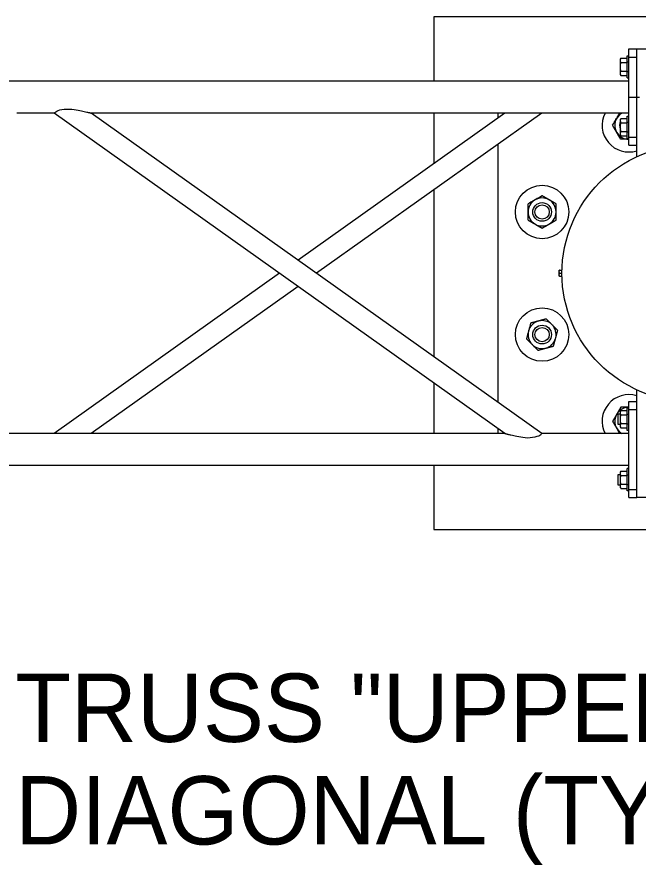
# Model space of a CAD drawing. Extents: x 99862 to 104211, y 98939 to 111076.
# Drawn here: x 101665.2 to 101810.6, y 101744.5 to 101943 of the extents above; entities that cross this region are included whole.
import ezdxf

# ---------------------------------------------------------------- set-up
doc = ezdxf.new("R2010")
doc.units = 0
for name, color, linetype in [('Level 2', 7, 'Continuous'), ('Level 20', 7, 'Continuous'), ('Level 3', 7, 'Continuous'), ('Level 4', 7, 'Continuous'), ('Level 5', 7, 'Continuous'), ('Level 6', 7, 'Continuous'), ('Level 9', 7, 'Continuous')]:
    doc.layers.add(name, color=color, linetype=linetype)

msp = doc.modelspace()

# ---------------------------------------------------------------- linework, layer by layer
at = {"layer": 'Level 2'}
for p, q in [((101882.76, 101942.97), (101762.76, 101942.97)), ((101762.76, 101942.97), (101762.76, 101927.97)), ((101762.76, 101920.47), (101762.76, 101908.62)), ((101777.76, 101920.47), (101777.76, 101919.29)), ((101777.76, 101913.15), (101777.76, 101852.78)), ((101762.76, 101902.49), (101762.76, 101863.45)), ((101762.76, 101857.31), (101762.76, 101845.47)), ((101777.76, 101846.65), (101777.76, 101845.47)), ((101762.76, 101837.97), (101762.76, 101822.97)), ((101762.76, 101822.97), (101882.76, 101822.97))]:
    msp.add_line(p, q, dxfattribs=at)
at = {"layer": 'Level 20'}
for p, q in [((101806.43, 101933.05), (101806.59, 101933.32)), ((101806.43, 101932.82), (101806.43, 101933.05)), ((101806.43, 101932.8), (101806.43, 101932.82)), ((101806.43, 101931.33), (101806.43, 101932.8)), ((101806.59, 101933.32), (101807.99, 101933.32)), ((101807.99, 101928.69), (101807.99, 101933.89)), ((101807.99, 101933.89), (101808.38, 101933.89)), ((101806.43, 101931.25), (101806.43, 101931.33)), ((101806.43, 101929.79), (101806.43, 101931.25)), ((101806.59, 101932.3), (101807.99, 101932.3)), ((101807.99, 101932.46), (101808.38, 101932.46)), ((101806.43, 101929.74), (101806.43, 101929.79)), ((101806.43, 101929.53), (101806.43, 101929.74)), ((101806.59, 101929.26), (101806.43, 101929.53)), ((101806.59, 101930.28), (101807.99, 101930.28)), ((101806.59, 101929.26), (101807.99, 101929.26)), ((101808.38, 101930.12), (101807.99, 101930.12)), ((101807.99, 101928.69), (101808.38, 101928.69)), ((101806.43, 101918.91), (101806.59, 101919.18)), ((101806.43, 101918.68), (101806.43, 101918.91)), ((101806.59, 101919.18), (101807.99, 101919.18)), ((101807.99, 101914.54), (101807.99, 101919.75)), ((101807.99, 101919.75), (101808.38, 101919.75)), ((101806.43, 101918.66), (101806.43, 101918.68)), ((101806.43, 101917.19), (101806.43, 101918.66)), ((101806.43, 101917.1), (101806.43, 101917.19)), ((101806.43, 101915.65), (101806.43, 101917.1)), ((101806.59, 101918.16), (101807.99, 101918.16)), ((101807.99, 101918.32), (101808.38, 101918.32)), ((101805.59, 101915.94), (101805.54, 101916.01)), ((101806.43, 101915.6), (101806.43, 101915.65)), ((101806.43, 101915.39), (101806.43, 101915.6)), ((101806.59, 101915.12), (101806.43, 101915.39)), ((101806.59, 101916.13), (101807.99, 101916.13)), ((101806.59, 101915.12), (101807.99, 101915.12)), ((101808.38, 101915.98), (101807.99, 101915.98)), ((101807.99, 101914.54), (101808.38, 101914.54)), ((101808.38, 101914.33), (101808.33, 101914.33)), ((101789.79, 101900.14), (101789.71, 101900.18)), ((101791.39, 101897.24), (101791.39, 101897.4)), ((101786.41, 101894.51), (101786.53, 101894.44)), ((101789.67, 101894.43), (101789.83, 101894.52)), ((101787.3, 101871.8), (101787.22, 101871.77)), ((101790.49, 101870.88), (101790.37, 101870.99)), ((101791.26, 101867.68), (101791.3, 101867.85)), ((101788.89, 101865.43), (101789.03, 101865.47)), ((101807.99, 101846.19), (101807.99, 101851.39)), ((101808.38, 101851.39), (101807.99, 101851.39)), ((101805.59, 101850), (101805.54, 101849.93)), ((101805.83, 101849.96), (101805.83, 101849.24)), ((101806.43, 101849.96), (101805.83, 101849.96)), ((101806.43, 101850.55), (101806.59, 101850.82)), ((101806.43, 101850.32), (101806.43, 101850.55)), ((101806.43, 101850.3), (101806.43, 101850.32)), ((101806.43, 101848.83), (101806.43, 101850.3)), ((101806.59, 101850.82), (101807.99, 101850.82)), ((101806.59, 101849.8), (101807.99, 101849.8)), ((101807.99, 101849.96), (101808.38, 101849.96)), ((101805.83, 101849.24), (101805.83, 101847.62)), ((101805.83, 101847.62), (101806.43, 101847.62)), ((101806.43, 101848.75), (101806.43, 101848.83)), ((101806.43, 101847.29), (101806.43, 101848.75)), ((101806.59, 101847.78), (101807.99, 101847.78)), ((101808.38, 101847.62), (101807.99, 101847.62)), ((101806.43, 101847.24), (101806.43, 101847.29)), ((101806.43, 101847.03), (101806.43, 101847.24)), ((101806.59, 101846.76), (101806.43, 101847.03)), ((101806.59, 101846.76), (101807.99, 101846.76)), ((101808.38, 101846.19), (101807.99, 101846.19)), ((101805.83, 101835.82), (101805.83, 101833.47)), ((101806.43, 101835.82), (101805.83, 101835.82)), ((101806.43, 101836.41), (101806.59, 101836.68)), ((101806.43, 101836.18), (101806.43, 101836.41)), ((101806.43, 101836.16), (101806.43, 101836.18)), ((101806.43, 101834.69), (101806.43, 101836.16)), ((101806.59, 101836.68), (101807.99, 101836.68)), ((101806.59, 101835.66), (101807.99, 101835.66)), ((101807.99, 101832.04), (101807.99, 101837.25)), ((101808.38, 101837.25), (101807.99, 101837.25)), ((101807.99, 101835.82), (101808.38, 101835.82)), ((101805.83, 101833.47), (101806.43, 101833.47)), ((101806.43, 101834.6), (101806.43, 101834.69)), ((101806.43, 101833.15), (101806.43, 101834.6)), ((101806.59, 101833.63), (101807.99, 101833.63)), ((101808.38, 101833.47), (101807.99, 101833.47)), ((101806.43, 101833.1), (101806.43, 101833.15)), ((101806.43, 101832.89), (101806.43, 101833.1)), ((101806.59, 101832.62), (101806.43, 101832.89)), ((101806.59, 101832.62), (101807.99, 101832.62)), ((101808.38, 101832.04), (101807.99, 101832.04))]:
    msp.add_line(p, q, dxfattribs=at)
for centre, radius in [((101788.11, 101897.32), 2.19), ((101788.11, 101897.32), 1.67), ((101788.11, 101868.62), 2.19), ((101788.11, 101868.62), 1.67)]:
    msp.add_circle(centre, radius, dxfattribs=at)
for centre, radius, start, end in [((101808.41, 101917.61), 3.28, 119.5283, 209.2446), ((101808.41, 101917.61), 2.19, 154.6918, 205.3082), ((101808.41, 101917.61), 3.28, 210.758, 268.5832), ((101788.11, 101897.32), 3.28, 60.7554, 180), ((101788.11, 101897.32), 3.28, 1.4168, 59.242), ((101788.11, 101897.32), 3.28, 180, 238.8031), ((101788.11, 101897.32), 3.28, 301.5608, 358.5832), ((101788.11, 101897.32), 3.28, 241.1969, 298.4392), ((101788.11, 101868.62), 3.28, 105.7554, 225), ((101788.11, 101868.62), 3.28, 46.4168, 104.242), ((101788.11, 101868.62), 3.28, 346.5608, 43.5832), ((101788.11, 101868.62), 3.28, 286.1969, 343.4392), ((101788.11, 101868.62), 3.28, 225, 283.8031), ((101808.41, 101848.32), 3.28, 91.4168, 149.242), ((101808.41, 101848.32), 3.28, 150.7554, 240.4717)]:
    msp.add_arc(centre, radius, start, end, dxfattribs=at)
for points, degree in [([(101806.43, 101932.82), (101806.43, 101932.99), (101806.49, 101933.16), (101806.59, 101933.32)], 2), ([(101806.59, 101932.3), (101806.49, 101932.47), (101806.43, 101932.63), (101806.43, 101932.8)], 2), ([(101806.43, 101931.33), (101806.43, 101931.66), (101806.49, 101931.99), (101806.59, 101932.3)], 2), ([(101806.59, 101930.28), (101806.49, 101930.59), (101806.43, 101930.92), (101806.43, 101931.25)], 2), ([(101806.43, 101929.79), (101806.43, 101929.96), (101806.49, 101930.12), (101806.59, 101930.28)], 2), ([(101806.59, 101929.26), (101806.49, 101929.42), (101806.43, 101929.58), (101806.43, 101929.74)], 2), ([(101806.57, 101929.29), (101806.57, 101929.28), (101806.58, 101929.27), (101806.59, 101929.26)], 2), ([(101804.62, 101917.61), (101804.93, 101918.15), (101805.24, 101918.69), (101805.8, 101919.66), (101806.03, 101920.07), (101806.27, 101920.47)], 3), ([(101806.43, 101918.68), (101806.43, 101918.85), (101806.49, 101919.02), (101806.59, 101919.18)], 2), ([(101805.54, 101916.01), (101805.23, 101916.56), (101804.92, 101917.09), (101804.62, 101917.61)], 2), ([(101806.59, 101918.16), (101806.49, 101918.32), (101806.43, 101918.49), (101806.43, 101918.66)], 2), ([(101806.43, 101917.19), (101806.43, 101917.52), (101806.49, 101917.85), (101806.59, 101918.16)], 2), ([(101806.59, 101916.13), (101806.49, 101916.45), (101806.43, 101916.78), (101806.43, 101917.1)], 2), ([(101806.51, 101914.33), (101806.21, 101914.86), (101805.9, 101915.39), (101805.59, 101915.94)], 2), ([(101806.43, 101915.65), (101806.43, 101915.81), (101806.49, 101915.98), (101806.59, 101916.13)], 2), ([(101806.59, 101915.12), (101806.49, 101915.28), (101806.43, 101915.44), (101806.43, 101915.6)], 2), ([(101806.57, 101915.15), (101806.57, 101915.14), (101806.58, 101915.13), (101806.59, 101915.12)], 2), ([(101808.33, 101914.33), (101807.71, 101914.33), (101807.1, 101914.33), (101806.51, 101914.33)], 2), ([(101788.11, 101901.11), (101787.57, 101900.8), (101787.03, 101900.48), (101785.92, 101899.84), (101785.37, 101899.52), (101784.83, 101899.21)], 3), ([(101789.71, 101900.18), (101789.17, 101900.5), (101788.63, 101900.8), (101788.11, 101901.11)], 2), ([(101784.83, 101897.32), (101784.83, 101897.96), (101784.83, 101898.6), (101784.83, 101899.21)], 2), ([(101791.39, 101899.21), (101790.87, 101899.52), (101790.33, 101899.82), (101789.79, 101900.14)], 2), ([(101791.39, 101897.4), (101791.39, 101898.01), (101791.39, 101898.63), (101791.39, 101899.21)], 2), ([(101784.83, 101895.42), (101784.83, 101896.04), (101784.83, 101896.68), (101784.83, 101897.32)], 2), ([(101791.39, 101895.42), (101791.39, 101896.01), (101791.39, 101896.62), (101791.39, 101897.24)], 2), ([(101784.83, 101895.42), (101785.35, 101895.13), (101785.87, 101894.82), (101786.41, 101894.51)], 2), ([(101789.83, 101894.52), (101790.36, 101894.83), (101790.88, 101895.13), (101791.39, 101895.42)], 2), ([(101786.53, 101894.44), (101787.07, 101894.13), (101787.59, 101893.83), (101788.11, 101893.53)], 2), ([(101788.11, 101893.53), (101788.62, 101893.83), (101789.14, 101894.13), (101789.67, 101894.43)], 2), ([(101785.43, 101871.3), (101785.27, 101870.7), (101785.11, 101870.09), (101784.78, 101868.85), (101784.61, 101868.23), (101784.45, 101867.64)], 3), ([(101787.22, 101871.77), (101786.61, 101871.61), (101786.02, 101871.45), (101785.43, 101871.3)], 2), ([(101789.09, 101872.28), (101788.51, 101872.12), (101787.91, 101871.96), (101787.3, 101871.8)], 2), ([(101790.37, 101870.99), (101789.94, 101871.43), (101789.51, 101871.86), (101789.09, 101872.28)], 2), ([(101791.77, 101869.6), (101791.35, 101870.01), (101790.92, 101870.45), (101790.49, 101870.88)], 2), ([(101791.3, 101867.85), (101791.46, 101868.45), (101791.62, 101869.03), (101791.77, 101869.6)], 2), ([(101785.79, 101866.3), (101785.34, 101866.75), (101784.89, 101867.2), (101784.45, 101867.64)], 2), ([(101790.79, 101865.94), (101790.94, 101866.51), (101791.1, 101867.09), (101791.26, 101867.68)], 2), ([(101787.13, 101864.96), (101786.69, 101865.39), (101786.24, 101865.84), (101785.79, 101866.3)], 2), ([(101787.13, 101864.96), (101787.71, 101865.11), (101788.29, 101865.27), (101788.89, 101865.43)], 2), ([(101789.03, 101865.47), (101789.63, 101865.63), (101790.21, 101865.78), (101790.79, 101865.94)], 2), ([(101806.51, 101851.6), (101806.21, 101851.08), (101805.9, 101850.55), (101805.59, 101850)], 2), ([(101808.33, 101851.6), (101807.71, 101851.6), (101807.1, 101851.6), (101806.51, 101851.6)], 2), ([(101805.54, 101849.93), (101805.23, 101849.38), (101804.92, 101848.85), (101804.62, 101848.32)], 2), ([(101806.43, 101850.32), (101806.43, 101850.49), (101806.49, 101850.66), (101806.59, 101850.82)], 2), ([(101806.59, 101849.8), (101806.49, 101849.97), (101806.43, 101850.13), (101806.43, 101850.3)], 2), ([(101806.43, 101848.83), (101806.43, 101849.16), (101806.49, 101849.49), (101806.59, 101849.8)], 2), ([(101804.62, 101848.32), (101804.93, 101847.79), (101805.24, 101847.24), (101805.8, 101846.27), (101806.03, 101845.87), (101806.27, 101845.47)], 3), ([(101806.59, 101847.78), (101806.49, 101848.09), (101806.43, 101848.42), (101806.43, 101848.75)], 2), ([(101806.43, 101847.29), (101806.43, 101847.46), (101806.49, 101847.62), (101806.59, 101847.78)], 2), ([(101806.59, 101846.76), (101806.49, 101846.92), (101806.43, 101847.08), (101806.43, 101847.24)], 2), ([(101806.57, 101846.79), (101806.57, 101846.78), (101806.58, 101846.77), (101806.59, 101846.76)], 2), ([(101806.43, 101836.18), (101806.43, 101836.35), (101806.49, 101836.52), (101806.59, 101836.68)], 2), ([(101806.59, 101835.66), (101806.49, 101835.82), (101806.43, 101835.99), (101806.43, 101836.16)], 2), ([(101806.43, 101834.69), (101806.43, 101835.02), (101806.49, 101835.35), (101806.59, 101835.66)], 2), ([(101806.59, 101833.63), (101806.49, 101833.95), (101806.43, 101834.28), (101806.43, 101834.6)], 2), ([(101806.43, 101833.15), (101806.43, 101833.31), (101806.49, 101833.48), (101806.59, 101833.63)], 2), ([(101806.59, 101832.62), (101806.49, 101832.78), (101806.43, 101832.94), (101806.43, 101833.1)], 2), ([(101806.57, 101832.65), (101806.57, 101832.64), (101806.58, 101832.63), (101806.59, 101832.62)], 2)]:
    msp.add_open_spline(points, degree=degree, dxfattribs=at)
at = {"layer": 'Level 3'}
for centre in [(101788.11, 101897.32), (101788.11, 101868.62)]:
    msp.add_circle(centre, 6.25, dxfattribs=at)
for centre, start, end in [((101808.41, 101917.61), 152.8209, 287.2194), ((101808.41, 101848.32), 72.7806, 207.1791)]:
    msp.add_arc(centre, 6.25, start, end, dxfattribs=at)
at = {"layer": 'Level 4'}
for p, q in [((101810.26, 101935.47), (101835.26, 101935.47)), ((101810.26, 101910.24), (101810.26, 101935.47)), ((101810.26, 101830.47), (101810.26, 101855.7)), ((101835.26, 101830.47), (101810.26, 101830.47))]:
    msp.add_line(p, q, dxfattribs=at)
at = {"layer": 'Level 5'}
msp.add_circle((101822.76, 101882.97), 30, dxfattribs=at)
at = {"layer": 'Level 6'}
for p, q in [((101808.38, 101935.47), (101810.26, 101935.47)), ((101808.38, 101912.97), (101808.38, 101935.47)), ((101808.38, 101933.59), (101810.26, 101933.59)), ((101808.38, 101927.97), (100925.37, 101927.97)), ((101673.92, 101920.47), (101665.12, 101920.47)), ((101779.42, 101845.47), (101673.92, 101920.47)), ((101788.05, 101845.47), (101682.55, 101920.47)), ((101808.38, 101920.47), (101682.55, 101920.47)), ((101779.42, 101920.47), (101730.98, 101886.04)), ((101788.05, 101920.47), (101735.3, 101882.97)), ((101808.38, 101914.84), (101810.26, 101914.84)), ((101808.38, 101912.97), (101810.26, 101912.97)), ((101726.67, 101882.97), (101673.92, 101845.47)), ((101730.98, 101879.9), (101682.55, 101845.47)), ((101808.38, 101852.97), (101810.26, 101852.97)), ((101808.38, 101830.47), (101808.38, 101852.97)), ((101808.38, 101851.09), (101810.26, 101851.09)), ((101779.42, 101845.47), (101559.63, 101845.47)), ((101808.38, 101845.47), (101788.05, 101845.47)), ((101808.38, 101837.97), (100925.37, 101837.97)), ((101808.38, 101832.34), (101810.26, 101832.34)), ((101808.38, 101830.47), (101810.26, 101830.47))]:
    msp.add_line(p, q, dxfattribs=at)
for points, degree in [([(101673.92, 101920.47), (101673.92, 101920.47), (101673.94, 101920.46), (101674.08, 101920.7), (101675.47, 101921.45), (101678.19, 101921.41), (101679.92, 101921.09), (101681.37, 101920.75), (101681.72, 101920.67), (101682.01, 101920.6), (101682.24, 101920.54), (101682.42, 101920.5), (101682.51, 101920.48), (101682.54, 101920.47), (101682.55, 101920.47), (101682.55, 101920.47)], 3), ([(101673.92, 101920.47), (101673.92, 101920.47), (101673.92, 101920.47), (101673.92, 101920.47)], 2), ([(101682.55, 101920.47), (101682.55, 101920.47), (101682.55, 101920.47), (101682.54, 101920.47)], 2), ([(101779.45, 101845.46), (101779.43, 101845.47), (101779.42, 101845.47), (101779.42, 101845.47)], 2), ([(101779.42, 101845.47), (101779.42, 101845.47), (101779.44, 101845.46), (101779.55, 101845.44), (101779.72, 101845.39), (101779.96, 101845.34), (101780.25, 101845.26), (101780.6, 101845.18), (101780.99, 101845.09), (101782.6, 101844.77), (101784.57, 101844.34), (101787.27, 101844.77), (101788.02, 101845.45), (101788.04, 101845.46), (101788.05, 101845.47), (101788.05, 101845.47)], 3), ([(101788.05, 101845.47), (101788.05, 101845.47), (101788.04, 101845.47), (101788.04, 101845.47)], 2)]:
    msp.add_open_spline(points, degree=degree, dxfattribs=at)
at = {"layer": 'Level 9'}
for p, q in [((101808.38, 101924.22), (101810.88, 101924.22)), ((101792.13, 101883.34), (101792.13, 101883.67)), ((101792.13, 101883.3), (101792.13, 101883.34)), ((101792.13, 101882.63), (101792.13, 101883.3)), ((101792.19, 101883.67), (101792.76, 101883.67)), ((101792.13, 101882.6), (101792.13, 101882.63)), ((101792.13, 101882.27), (101792.13, 101882.6)), ((101792.19, 101882.97), (101792.76, 101882.97)), ((101792.19, 101882.27), (101792.76, 101882.27))]:
    msp.add_line(p, q, dxfattribs=at)
for points, degree in [([(101792.19, 101883.67), (101792.16, 101883.67), (101792.13, 101883.67), (101792.13, 101883.67)], 2), ([(101792.13, 101883.34), (101792.13, 101883.34), (101792.13, 101883.34), (101792.13, 101883.34), (101792.13, 101883.45), (101792.16, 101883.57), (101792.19, 101883.67)], 3), ([(101792.19, 101882.97), (101792.16, 101883.08), (101792.13, 101883.19), (101792.13, 101883.3)], 2), ([(101792.13, 101882.63), (101792.13, 101882.63), (101792.13, 101882.64), (101792.13, 101882.64), (101792.13, 101882.75), (101792.16, 101882.86), (101792.19, 101882.97)], 3), ([(101792.19, 101882.27), (101792.16, 101882.38), (101792.13, 101882.49), (101792.13, 101882.6)], 2), ([(101792.13, 101882.27), (101792.13, 101882.27), (101792.13, 101882.27), (101792.13, 101882.27)], 2), ([(101792.19, 101882.27), (101792.16, 101882.27), (101792.13, 101882.27), (101792.13, 101882.27)], 2)]:
    msp.add_open_spline(points, degree=degree, dxfattribs=at)

# ---------------------------------------------------------------- texts
at = {"layer": 'Level 20'}
for s, p in [('TRUSS "UPPER" HORIZONTAL', (101664.74, 101773.27)), ('DIAGONAL (TYP.)', (101664.74, 101749.27))]:
    msp.add_text(s, height=16, rotation=360, dxfattribs=at).set_placement(p)

doc.saveas('drawing.dxf')
